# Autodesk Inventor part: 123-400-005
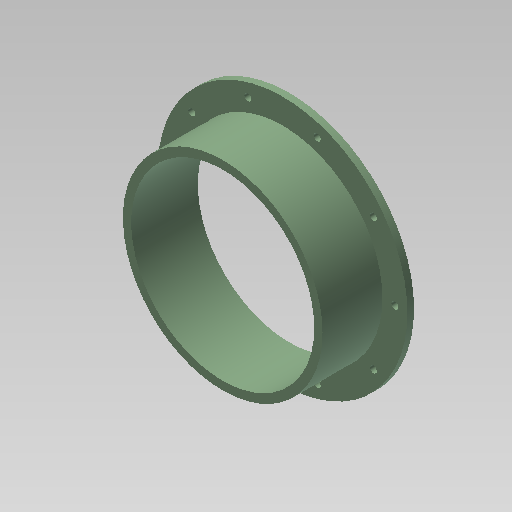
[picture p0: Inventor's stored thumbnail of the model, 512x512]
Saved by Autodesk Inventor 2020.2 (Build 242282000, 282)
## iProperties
Created: 2006-08
Part Number: 123-400-005
Material: Aluminium-6061
Document SubType Name: Modeling
Designer: F.Stasiak
Description: Podstawa głowicy
Mass: 32909.3 g
Surface Area: 11466.7 cm^2
Volume: 12143.7 cm^3
Density: 2.71 g/cm^3
Appearance: Zielony pastelowy
Manager: www.cadconsulting.pl
Company: Fabian Stasiak CAD Consulting
KODMAT: 13-1654
Author: F.Stasiak
Subject: Zbiór ćwiczeń. Autodesk Inventor 2020. Kurs podstawowy
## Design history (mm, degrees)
sketch "Szkic1"
  geometry: C1 r 375 at (0, 0); C2 r 300 at (0, 0); 1 further point
  constraints: 2 centre point, 2 coincident
  dimensions: "d0" = 750 diameter of C1; "d1" = 600 diameter of C2
extrude "Wyciągnięcie proste1" new body sketch "Szkic1" distance "d2" = 20; taper "d3" = 0 deg
extrude "Wyciągnięcie proste2" join sketch "Szkic1" distance "d4" = 200; taper "d5" = 0 deg
sketch "Szkic2"
  geometry: C1 r 300 at (0, 0) reference; C2 r 275 at (0, 0)
  constraints: 1 centre point, 1 coincident
  dimensions: "d6" = 550 diameter of C2
extrude "Wyciągnięcie proste3" cut sketch "Szkic2" extent not by distance; stored distance "d7" = 200; taper "d8" = 0 deg
sketch "Szkic3" dims "d9" = 675
  geometry: C1 r 375 at (0, 0) reference; 2 further points
  constraints: 2 horizontal alignment, 1 coincident, 2 other
hole "Otwór1" sketch "Szkic3" at (337.5, 0) diameter "d10" = 21; stored, may be unused: countersink angle "d14" = 90 deg, drill point angle "d16" = 118 deg; dims "d11" = 6, "d12" = 4, "d13" = 2, "d15" = 8
pattern_circular "Szyk kołowy1" dims angle "d18" = 360 deg
node "Bryła1"
node "Korpusy bryłowe"
node "Korpusy powierzchniowe"
